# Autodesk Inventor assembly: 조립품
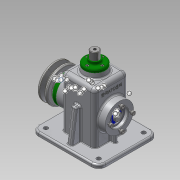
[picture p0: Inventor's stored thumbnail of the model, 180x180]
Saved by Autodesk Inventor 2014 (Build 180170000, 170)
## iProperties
Created: 2016-08
Part Number: 조립품
Document SubType Name: Assembly
Designer: user
Author: user
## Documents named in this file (19)
- C:\Users\user\Desktop\460820V1018\조립품.iam
- C:\Users\user\Desktop\460820V1018\본체.ipt
- C:\Users\user\Desktop\460820V1018\뒤커버.ipt
- C:\Users\user\Desktop\460820V1018\앞커버.ipt
- C:\Users\user\Desktop\460820V1018\상부부시.ipt
- C:\Users\user\Desktop\460820V1018\볼트 M3 x 8.ipt
- C:\Users\user\Desktop\460820V1018\볼트 M4 x 10.ipt
- C:\Users\user\Desktop\460820V1018\베어링 15 x 35 x 11.ipt
- C:\Users\user\Desktop\460820V1018\멈춤링 15 x 1.ipt
- C:\Users\user\Desktop\460820V1018\편심축.ipt
- C:\Users\user\Desktop\460820V1018\V-벨트풀리.ipt
- C:\Users\user\Desktop\460820V1018\고정핀.ipt
- C:\Users\user\Desktop\460820V1018\링크.ipt
- C:\Users\user\Desktop\460820V1018\멈춤링 6 x 5.ipt
- C:\Users\user\Desktop\460820V1018\볼트 M6 x 12.ipt
- C:\Users\user\Desktop\460820V1018\슬라이드바.ipt
- C:\Users\user\Desktop\460820V1018\오일실 15 25 7.ipt
- C:\Users\user\Desktop\460820V1018\와셔.ipt
- C:\Users\user\Desktop\460820V1018\키 5 x 5 x 14.ipt
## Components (15 placed, 5 different names)
1. V-벨트풀리:1 — 각도:1
2. 고정핀:1
3. ISO 4018 M6 x 12:1 — 각도:2
4. ISO 4762 M4 x 10:2 — 강체:3
5. ISO 4762 M4 x 10:3
6. ISO 4762 M4 x 10:4
7. ISO 4762 M4 x 10:5
8. ISO 4762 M3 x 8:1 — 강체:2
9. ISO 4762 M3 x 8:2
10. ISO 4762 M3 x 8:3
11. ISO 4762 M3 x 8:4
12. ISO 4762 M4 x 10:1 — 강체:1
13. ISO 4762 M4 x 10:6
14. ISO 4762 M4 x 10:7
15. ISO 4762 M4 x 10:8
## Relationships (5: WeldJoint 3, Angle 2)
- 강체:1 [WeldJoint]: ISO 4762 M4 x 10:1
- 강체:2 [WeldJoint]: ISO 4762 M3 x 8:1
- 강체:3 [WeldJoint]: ISO 4762 M4 x 10:2
- 각도:1 [Angle]: V-벨트풀리:1
- 각도:2 [Angle]: ISO 4018 M6 x 12:1
